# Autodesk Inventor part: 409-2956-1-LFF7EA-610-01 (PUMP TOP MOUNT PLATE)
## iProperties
Created: 2011-01
Part Number: 409-2956-1-LFF7EA-610-01 (PUMP TOP MOUNT PLATE)
Cost Center: 0 lbmass
Material: A36 STEEL PLATE
Document SubType Name: Sheet Metal
Designer: S. Boerckel
Authority: 0 in^3
Mass: 2841.15 g
Surface Area: 700.573 cm^2
Volume: 361.469 cm^3
Density: 7.86 g/cm^3
Flat Pattern Width: 7.62 cm
Flat Pattern Length: 38.1 cm
Flat Pattern Area: 290.322 cm^2
Sheet Metal Rule: 1/2"Thk
Author: S. Boerckel
Revision Number: 0
SaveDate: 2008-01-15
SaveTime: 10:24
FileName: Sheet Metal
Wide: =<Flat Pattern Width>cm
Length: =<Flat Pattern Length>cm
Thickness: 0.5000 in
SMR: =<Sheet Metal Rule> - <Material>
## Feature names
1. Hole1
2. Plate1
